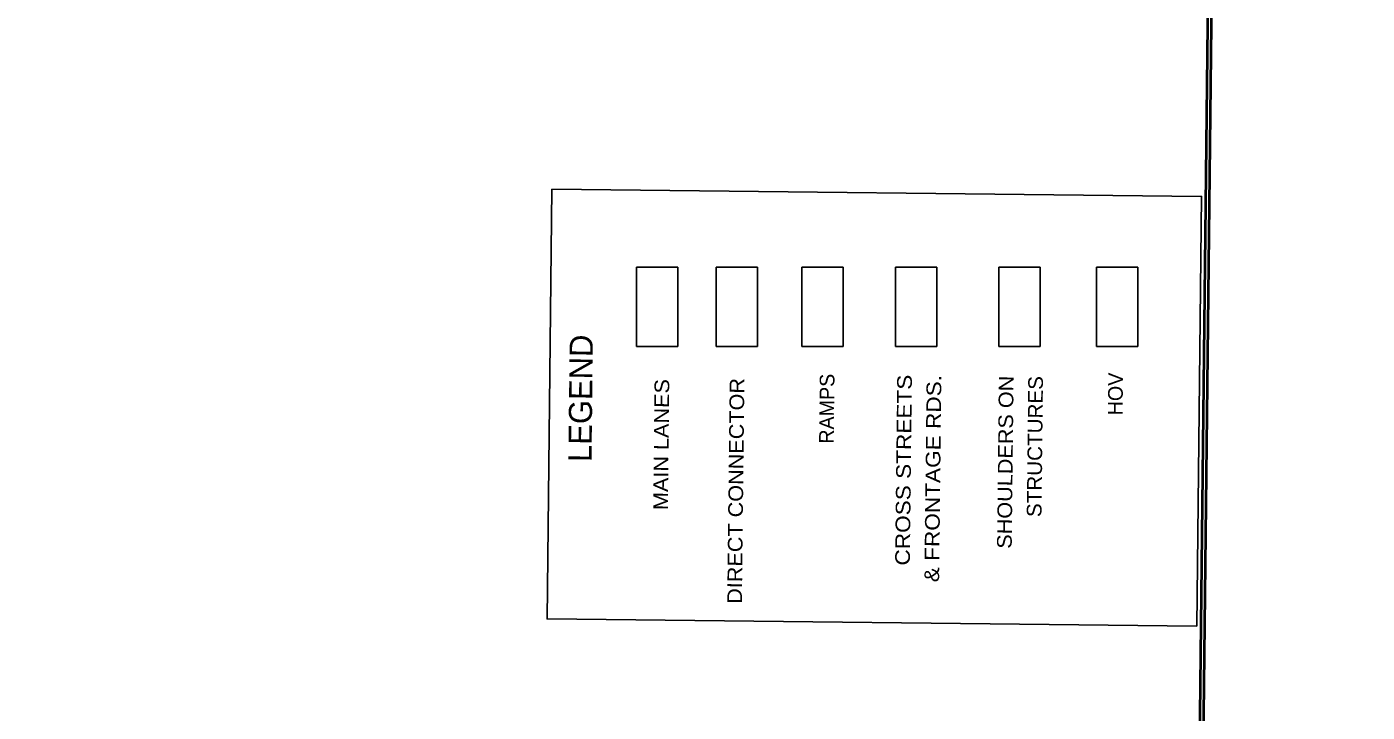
# Model space of a CAD drawing. Extents: x 2356576 to 2377878, y 6966390 to 6990634.
# Drawn here: x 2365341 to 2367164, y 6969888 to 6970821 of the extents above; entities that cross this region are included whole.
import ezdxf
from ezdxf.enums import TextEntityAlignment as Align

# ---------------------------------------------------------------- set-up
doc = ezdxf.new("R2010")
doc.units = 0
doc.header["$LTSCALE"] = 7.1
doc.layers.add('19', color=7, linetype='Continuous', lineweight=13)
doc.layers.add('8', color=7, linetype='Continuous', lineweight=13)

msp = doc.modelspace()

# ---------------------------------------------------------------- linework, layer by layer
at = {"layer": '19', "lineweight": 40}
msp.add_lwpolyline([(2363758.773, 6990629.355), (2367158.576, 6990592.767), (2366922.891, 6968646.236), (2363523.088, 6968682.826)], close=True, dxfattribs=at)
at = {"layer": '19', "lineweight": 25}
msp.add_lwpolyline([(2366931.855, 6970005.542), (2366938.347, 6970590.182), (2366054.887, 6970599.994), (2366048.395, 6970015.354)], close=True, dxfattribs=at)
at = {"layer": '19'}
for points in [[(2366169.809, 6970494.202), (2366226.073, 6970494.202), (2366226.073, 6970386.16), (2366169.809, 6970386.16)], [(2366169.809, 6970386.16), (2366226.073, 6970386.16), (2366226.073, 6970494.202), (2366169.809, 6970494.202)], [(2366278.321, 6970494.202), (2366334.585, 6970494.202), (2366334.585, 6970386.16), (2366278.321, 6970386.16)], [(2366278.321, 6970386.16), (2366334.585, 6970386.16), (2366334.585, 6970494.202), (2366278.321, 6970494.202)], [(2366394.873, 6970494.202), (2366451.137, 6970494.202), (2366451.137, 6970386.16), (2366394.873, 6970386.16)], [(2366394.873, 6970386.16), (2366451.137, 6970386.16), (2366451.137, 6970494.202), (2366394.873, 6970494.202)], [(2366522.141, 6970494.202), (2366578.405, 6970494.202), (2366578.405, 6970386.16), (2366522.141, 6970386.16)], [(2366522.141, 6970386.16), (2366578.405, 6970386.16), (2366578.405, 6970494.202), (2366522.141, 6970494.202)], [(2366662.803, 6970494.202), (2366719.067, 6970494.202), (2366719.067, 6970386.16), (2366662.803, 6970386.16)], [(2366662.803, 6970386.16), (2366719.067, 6970386.16), (2366719.067, 6970494.202), (2366662.803, 6970494.202)], [(2366795.431, 6970494.202), (2366851.695, 6970494.202), (2366851.695, 6970386.16), (2366795.431, 6970386.16)], [(2366795.431, 6970386.16), (2366851.695, 6970386.16), (2366851.695, 6970494.202), (2366795.431, 6970494.202)]]:
    msp.add_lwpolyline(points, close=True, dxfattribs=at)
at = {"layer": '8', "lineweight": 40}
for points in [[(2363753.827, 6990634.409), (2367163.63, 6990597.713), (2366927.837, 6968641.182), (2363518.034, 6968677.88)], [(2363758.773, 6990629.355), (2367158.576, 6990592.767), (2366922.891, 6968646.236), (2363523.088, 6968682.826)]]:
    msp.add_lwpolyline(points, close=True, dxfattribs=at)
at = {"layer": '8', "lineweight": 25}
msp.add_lwpolyline([(2366931.855, 6970005.542), (2366938.347, 6970590.182), (2366054.887, 6970599.994), (2366048.395, 6970015.354)], close=True, dxfattribs=at)
at = {"layer": '8'}
for points in [[(2366169.809, 6970494.202), (2366226.073, 6970494.202), (2366226.073, 6970386.16), (2366169.809, 6970386.16)], [(2366169.809, 6970386.16), (2366226.073, 6970386.16), (2366226.073, 6970494.202), (2366169.809, 6970494.202)], [(2366278.321, 6970494.202), (2366334.585, 6970494.202), (2366334.585, 6970386.16), (2366278.321, 6970386.16)], [(2366278.321, 6970386.16), (2366334.585, 6970386.16), (2366334.585, 6970494.202), (2366278.321, 6970494.202)], [(2366394.873, 6970494.202), (2366451.137, 6970494.202), (2366451.137, 6970386.16), (2366394.873, 6970386.16)], [(2366394.873, 6970386.16), (2366451.137, 6970386.16), (2366451.137, 6970494.202), (2366394.873, 6970494.202)], [(2366522.141, 6970494.202), (2366578.405, 6970494.202), (2366578.405, 6970386.16), (2366522.141, 6970386.16)], [(2366522.141, 6970386.16), (2366578.405, 6970386.16), (2366578.405, 6970494.202), (2366522.141, 6970494.202)], [(2366662.803, 6970494.202), (2366719.067, 6970494.202), (2366719.067, 6970386.16), (2366662.803, 6970386.16)], [(2366662.803, 6970386.16), (2366719.067, 6970386.16), (2366719.067, 6970494.202), (2366662.803, 6970494.202)], [(2366795.431, 6970494.202), (2366851.695, 6970494.202), (2366851.695, 6970386.16), (2366795.431, 6970386.16)], [(2366795.431, 6970386.16), (2366851.695, 6970386.16), (2366851.695, 6970494.202), (2366795.431, 6970494.202)]]:
    msp.add_lwpolyline(points, close=True, dxfattribs=at)

# ---------------------------------------------------------------- texts
at = {"layer": '19'}
msp.add_text('LEGEND', height=31.5, rotation=89.364, dxfattribs=at).set_placement((2366109.729, 6970315.409), align=Align.CENTER)
for s, p in [('RAMPS', (2366439.265, 6970348.839)), ('HOV', (2366831.554, 6970350.29))]:
    msp.add_text(s, height=20, rotation=89.364, dxfattribs=at).set_placement(p, align=Align.RIGHT)
for s, width, p in [('CROSS STREETS', 1.15, (2366544.54, 6970347.611)), ('& FRONTAGE RDS.', 1.15, (2366584.538, 6970347.167)), ('SHOULDERS ON', 1.1, (2366682.798, 6970346.158)), ('STRUCTURES', 1.05, (2366722.797, 6970345.715)), ('MAIN LANES', 1.1, (2366214.601, 6970341.578)), ('DIRECT CONNECTOR', 1.1, (2366316.703, 6970343.029))]:
    msp.add_text(s, height=20, rotation=89.364, dxfattribs=dict(at, width=width)).set_placement(p, align=Align.RIGHT)
at = {"layer": '8'}
msp.add_text('LEGEND', height=31.5, rotation=89.364, dxfattribs=at).set_placement((2366109.729, 6970315.409), align=Align.CENTER)
for s, p in [('RAMPS', (2366439.265, 6970348.839)), ('HOV', (2366831.554, 6970350.29))]:
    msp.add_text(s, height=20, rotation=89.364, dxfattribs=at).set_placement(p, align=Align.RIGHT)
for s, width, p in [('CROSS STREETS', 1.15, (2366544.54, 6970347.611)), ('& FRONTAGE RDS.', 1.15, (2366584.538, 6970347.167)), ('SHOULDERS ON', 1.1, (2366682.798, 6970346.158)), ('STRUCTURES', 1.05, (2366722.797, 6970345.715)), ('MAIN LANES', 1.1, (2366214.601, 6970341.578)), ('DIRECT CONNECTOR', 1.1, (2366316.703, 6970343.029))]:
    msp.add_text(s, height=20, rotation=89.364, dxfattribs=dict(at, width=width)).set_placement(p, align=Align.RIGHT)

doc.saveas('drawing.dxf')
